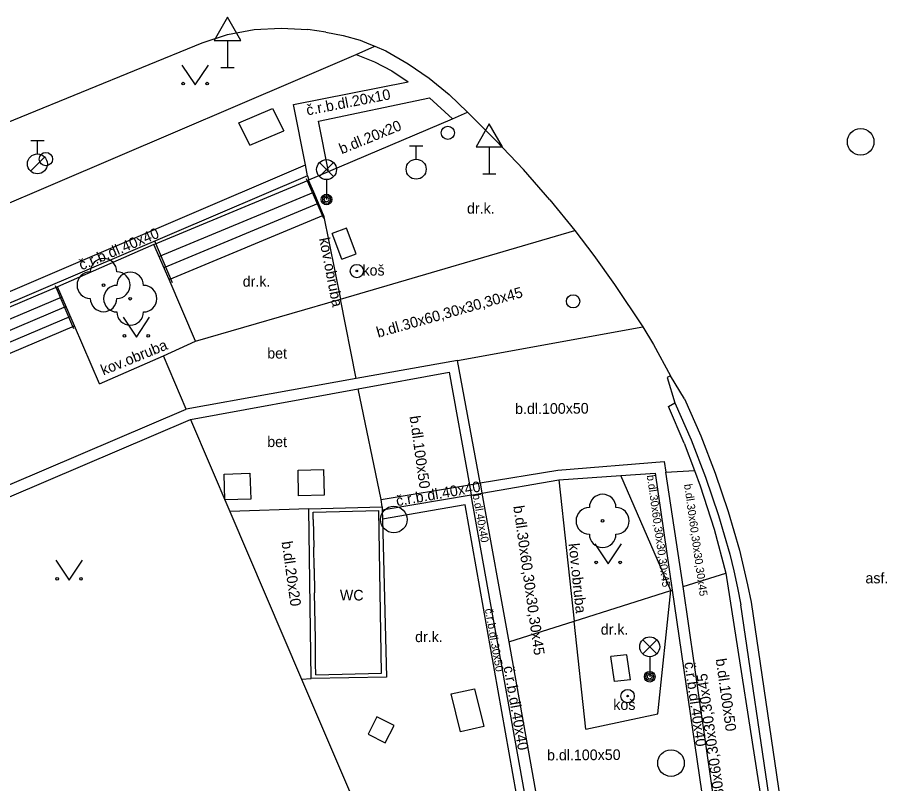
# Model space of a CAD drawing. Extents: x -600309 to -598967, y -1161267 to -1160292.
# Drawn here: x -599340.27 to -599307.71, y -1161175.51 to -1161146.69 of the extents above; entities that cross this region are included whole.
import ezdxf

# ---------------------------------------------------------------- set-up
doc = ezdxf.new("R2010")
doc.units = 0
for name, color, linetype in [('Level 10', 7, 'Continuous'), ('Level 11', 7, 'Continuous'), ('Level 22', 7, 'Continuous'), ('Level 24', 7, 'Continuous'), ('Level 25', 7, 'Continuous'), ('Level 26', 7, 'Continuous'), ('Level 27', 7, 'Continuous'), ('Level 28', 7, 'Continuous'), ('Level 31', 7, 'Continuous'), ('Level 33', 7, 'Continuous'), ('Level 34', 7, 'Continuous'), ('Level 36', 7, 'Continuous'), ('Level 40', 7, 'Continuous'), ('Level 41', 7, 'Continuous'), ('Level 42', 7, 'Continuous'), ('Level 5', 7, 'Continuous'), ('Level 6', 7, 'Continuous'), ('Level 9', 7, 'Continuous')]:
    doc.layers.add(name, color=color, linetype=linetype)

msp = doc.modelspace()

# ---------------------------------------------------------------- linework, layer by layer
at = {"layer": 'Level 10'}
for points in [[(-599333.33, -1161147.64), (-599332.37, -1161147.33), (-599331.37, -1161147.15), (-599330.36, -1161147.09), (-599329.35, -1161147.15)], [(-599328.68, -1161147.24), (-599329.35, -1161147.15)], [(-599328.68, -1161147.24), (-599328.03, -1161147.37), (-599327.38, -1161147.55)], [(-599327.38, -1161147.55), (-599327.06, -1161147.68), (-599326.83, -1161147.77), (-599326.42, -1161147.95)], [(-599344.68, -1161152.29), (-599333.33, -1161147.64)], [(-599326.42, -1161147.95), (-599325.58, -1161148.43), (-599324.79, -1161148.98), (-599324.04, -1161149.59), (-599323.35, -1161150.26)], [(-599323.35, -1161150.26), (-599322.28, -1161151.32), (-599321.25, -1161152.41)], [(-599320.26, -1161153.55), (-599321.25, -1161152.41)], [(-599320.26, -1161153.55), (-599319.32, -1161154.71), (-599318.6, -1161155.65), (-599317.82, -1161156.74)], [(-599317.82, -1161156.74), (-599316.76, -1161158.33), (-599316.36, -1161158.99), (-599315.72, -1161160.17)], [(-599315.19, -1161161.04), (-599315.72, -1161160.17)], [(-599315.19, -1161161.04), (-599314.58, -1161162.43), (-599314.04, -1161163.84), (-599313.55, -1161165.28), (-599313.13, -1161166.73)], [(-599313.13, -1161166.73), (-599312.97, -1161167.38), (-599312.82, -1161168.03), (-599312.69, -1161168.69)], [(-599312.69, -1161168.69), (-599310.5, -1161183.56)]]:
    msp.add_lwpolyline(points, dxfattribs=at)
at = {"layer": 'Level 11'}
for points in [[(-599327.53, -1161148.08), (-599326.83, -1161147.77)], [(-599329.73, -1161149.02), (-599327.53, -1161148.08)], [(-599327.53, -1161148.08), (-599326.85, -1161148.36), (-599326.19, -1161148.7), (-599325.58, -1161149.11)], [(-599343.45, -1161154.89), (-599329.73, -1161149.02)], [(-599329.89, -1161149.97), (-599325.58, -1161149.11)], [(-599328.95, -1161150.59), (-599324.78, -1161149.72)], [(-599324.78, -1161149.72), (-599323.91, -1161150.5)], [(-599329.44, -1161152.24), (-599329.89, -1161149.97)], [(-599323.91, -1161150.5), (-599323.35, -1161150.26)], [(-599329.33, -1161152.81), (-599329.31, -1161152.8), (-599328.57, -1161152.49), (-599323.91, -1161150.5)], [(-599328.57, -1161152.49), (-599328.95, -1161150.59)], [(-599348.91, -1161160.57), (-599329.44, -1161152.24)], [(-599329.36, -1161152.65), (-599329.44, -1161152.24)], [(-599329.36, -1161152.65), (-599351.42, -1161162.08)], [(-599329.36, -1161152.65), (-599329.31, -1161152.8)], [(-599335.14, -1161155.23), (-599329.33, -1161152.81)], [(-599329.13, -1161153.26), (-599329.33, -1161152.81)], [(-599334.95, -1161155.68), (-599329.13, -1161153.26)], [(-599328.95, -1161153.68), (-599329.13, -1161153.26)], [(-599334.76, -1161156.1), (-599328.95, -1161153.68)], [(-599328.76, -1161154.13), (-599328.95, -1161153.68)], [(-599334.57, -1161156.55), (-599328.76, -1161154.13)], [(-599328.76, -1161154.13), (-599328.13, -1161157.29)], [(-599328.13, -1161157.29), (-599319.32, -1161154.71)], [(-599335.14, -1161155.23), (-599338.77, -1161156.82)], [(-599333.57, -1161158.87), (-599334.57, -1161156.55), (-599335.14, -1161155.23)], [(-599338.77, -1161156.82), (-599351.32, -1161162.15)], [(-599338.13, -1161158.29), (-599338.77, -1161156.82)], [(-599338.6, -1161157.21), (-599351.14, -1161162.53)], [(-599333.57, -1161158.87), (-599328.13, -1161157.29)], [(-599327.53, -1161160.27), (-599328.13, -1161157.29)], [(-599338.44, -1161157.57), (-599350.99, -1161162.9)], [(-599338.28, -1161157.94), (-599350.84, -1161163.27)], [(-599343.98, -1161160.78), (-599338.13, -1161158.29)], [(-599337.19, -1161160.47), (-599338.13, -1161158.29)], [(-599323.73, -1161159.59), (-599316.76, -1161158.33)], [(-599334.78, -1161159.42), (-599333.57, -1161158.87)], [(-599337.19, -1161160.47), (-599334.78, -1161159.42)], [(-599333.93, -1161161.43), (-599334.78, -1161159.42)], [(-599323.73, -1161159.59), (-599327.53, -1161160.27)], [(-599322.88, -1161164.2), (-599323.73, -1161159.59)], [(-599327.46, -1161160.66), (-599324.04, -1161160.04)], [(-599324.04, -1161160.04), (-599323.27, -1161164.27)], [(-599315.72, -1161160.17), (-599315.85, -1161160.24)], [(-599315.85, -1161160.24), (-599315.55, -1161161.19)], [(-599327.53, -1161160.27), (-599333.93, -1161161.43)], [(-599333.77, -1161161.81), (-599327.46, -1161160.66)], [(-599326.6, -1161164.83), (-599327.46, -1161160.66)], [(-599315.8, -1161161.32), (-599315.55, -1161161.19)], [(-599315.55, -1161161.19), (-599314.94, -1161162.58), (-599314.4, -1161163.99), (-599313.91, -1161165.43), (-599313.49, -1161166.88)], [(-599348.49, -1161167.65), (-599333.93, -1161161.43)], [(-599315.21, -1161162.71), (-599315.8, -1161161.32)], [(-599348.68, -1161168.18), (-599333.77, -1161161.81)], [(-599333.77, -1161161.81), (-599332.29, -1161165.28)], [(-599315.21, -1161162.71), (-599314.82, -1161163.73), (-599314.6, -1161164.31), (-599314.08, -1161165.94), (-599313.64, -1161167.6)], [(-599319.95, -1161163.72), (-599315.96, -1161163.39)], [(-599315.96, -1161163.39), (-599315.9, -1161163.8)], [(-599322.88, -1161164.2), (-599319.95, -1161163.72)], [(-599317.58, -1161163.92), (-599316.3, -1161163.83)], [(-599316.3, -1161163.83), (-599315.66, -1161168.23), (-599314.38, -1161177)], [(-599315.9, -1161163.8), (-599314.82, -1161163.73)], [(-599315.24, -1161168.1), (-599315.9, -1161163.8)], [(-599322.81, -1161164.59), (-599319.92, -1161164.09)], [(-599319.92, -1161164.09), (-599317.58, -1161163.92)], [(-599319.92, -1161164.09), (-599319.34, -1161169.4)], [(-599315.71, -1161168.25), (-599317.58, -1161163.92)], [(-599326.6, -1161164.83), (-599323.27, -1161164.27)], [(-599323.27, -1161164.27), (-599322.88, -1161164.2)], [(-599323.27, -1161164.27), (-599323.21, -1161164.66)], [(-599322.88, -1161164.2), (-599322.81, -1161164.59)], [(-599323.21, -1161164.66), (-599326.56, -1161165.23)], [(-599323.21, -1161164.66), (-599322.81, -1161164.59)], [(-599320.92, -1161177.44), (-599323.21, -1161164.66)], [(-599322.81, -1161164.59), (-599321.8, -1161170.18), (-599320.5, -1161177.41)], [(-599326.56, -1161165.1), (-599326.6, -1161164.83)], [(-599323.44, -1161165.03), (-599326.55, -1161165.57)], [(-599321.23, -1161177.46), (-599323.44, -1161165.03)], [(-599329.32, -1161165.18), (-599332.29, -1161165.28)], [(-599332.29, -1161165.28), (-599329.59, -1161171.58)], [(-599313.49, -1161166.88), (-599313.34, -1161167.51), (-599313.2, -1161168.15), (-599313.08, -1161168.79)], [(-599315.24, -1161168.1), (-599313.64, -1161167.6)], [(-599313.64, -1161167.6), (-599312.2, -1161176.85)], [(-599319.34, -1161169.4), (-599315.71, -1161168.25)], [(-599316.2, -1161172.89), (-599315.71, -1161168.25)], [(-599315.71, -1161168.25), (-599315.66, -1161168.23)], [(-599313.96, -1161176.97), (-599315.24, -1161168.1)], [(-599310.84, -1161183.94), (-599313.08, -1161168.79)], [(-599321.8, -1161170.18), (-599319.34, -1161169.4)], [(-599318.9, -1161173.46), (-599319.34, -1161169.4)], [(-599329.59, -1161171.58), (-599329.23, -1161171.56)], [(-599329.59, -1161171.58), (-599327.07, -1161177.46)], [(-599318.9, -1161173.46), (-599316.2, -1161172.89)]]:
    msp.add_lwpolyline(points, dxfattribs=at)
at = {"layer": 'Level 22'}
for centre in [(-599337.03, -1161156.76), (-599336.03, -1161157.27), (-599318.27, -1161165.63)]:
    msp.add_circle(centre, 0.05, dxfattribs=at)
for centre, start, end in [((-599337.03, -1161156.26), 0, 180), ((-599337.53, -1161156.76), 90, 270), ((-599336.53, -1161156.76), 270, 90), ((-599336.03, -1161156.77), 0, 180), ((-599336.53, -1161157.27), 90, 270), ((-599335.53, -1161157.27), 270, 90), ((-599337.03, -1161157.26), 180, 0), ((-599336.03, -1161157.77), 180, 0), ((-599318.27, -1161165.13), 0, 180), ((-599318.77, -1161165.63), 90, 270), ((-599317.77, -1161165.63), 270, 90), ((-599318.27, -1161166.13), 180, 0)]:
    msp.add_arc(centre, 0.5, start, end, dxfattribs=at)
at = {"layer": 'Level 24'}
for points in [[(-599327.9, -1161154.62), (-599328.44, -1161154.82)], [(-599327.54, -1161155.58), (-599327.9, -1161154.62)], [(-599328.08, -1161155.78), (-599328.44, -1161154.82)], [(-599328.08, -1161155.78), (-599327.54, -1161155.58)], [(-599329.32, -1161165.18), (-599326.56, -1161165.1)], [(-599326.56, -1161165.1), (-599326.56, -1161165.23), (-599326.55, -1161165.57), (-599326.4, -1161171.51)], [(-599329.23, -1161171.56), (-599329.32, -1161165.18)], [(-599317.36, -1161170.67), (-599317.96, -1161170.73)], [(-599317.22, -1161171.61), (-599317.36, -1161170.67)], [(-599317.82, -1161171.67), (-599317.96, -1161170.73)], [(-599326.4, -1161171.51), (-599329.23, -1161171.56)], [(-599317.22, -1161171.61), (-599317.82, -1161171.67)]]:
    msp.add_lwpolyline(points, dxfattribs=at)
at = {"layer": 'Level 25'}
for centre, radius in [((-599327.51, -1161156.23), 0.25), ((-599327.51, -1161156.23), 0.0303), ((-599317.33, -1161172.22), 0.25), ((-599317.33, -1161172.22), 0.0303)]:
    msp.add_circle(centre, radius, dxfattribs=at)
at = {"layer": 'Level 26'}
for points in [[(-599331.95, -1161150.65), (-599330.68, -1161150.11)], [(-599330.68, -1161150.11), (-599330.26, -1161150.96)], [(-599331.53, -1161151.5), (-599331.95, -1161150.65)], [(-599331.53, -1161151.5), (-599330.26, -1161150.96)], [(-599332.5, -1161163.87), (-599331.53, -1161163.83)], [(-599331.53, -1161163.83), (-599331.5, -1161164.81)], [(-599329.72, -1161163.72), (-599328.76, -1161163.7)], [(-599329.71, -1161164.69), (-599329.72, -1161163.72)], [(-599328.76, -1161163.7), (-599328.74, -1161164.66)], [(-599332.47, -1161164.84), (-599332.5, -1161163.87)], [(-599331.5, -1161164.81), (-599332.47, -1161164.84)], [(-599328.74, -1161164.66), (-599329.71, -1161164.69)], [(-599323.96, -1161172.13), (-599323.09, -1161171.95)], [(-599323.09, -1161171.95), (-599322.74, -1161173.36)], [(-599323.62, -1161173.56), (-599323.96, -1161172.13)], [(-599326.76, -1161173), (-599327.09, -1161173.65)], [(-599326.11, -1161173.33), (-599326.76, -1161173)], [(-599326.44, -1161173.98), (-599326.11, -1161173.33)], [(-599322.74, -1161173.36), (-599323.62, -1161173.56)], [(-599327.09, -1161173.65), (-599326.44, -1161173.98)]]:
    msp.add_lwpolyline(points, dxfattribs=at)
at = {"layer": 'Level 27'}
for centre in [(-599308.57, -1161151.37), (-599326.12, -1161165.58), (-599315.7, -1161174.74)]:
    msp.add_circle(centre, 0.5, dxfattribs=at)
at = {"layer": 'Level 28'}
for p, q in [((-599339.77, -1161151.325), (-599339.27, -1161151.325)), ((-599339.52, -1161151.825), (-599339.52, -1161151.325)), ((-599325.53, -1161151.525), (-599325.03, -1161151.525)), ((-599325.28, -1161152.025), (-599325.28, -1161151.525)), ((-599339.778, -1161152.472), (-599339.248, -1161151.942))]:
    msp.add_line(p, q, dxfattribs=at)
for centre, radius in [((-599324.09, -1161151.03), 0.25), ((-599339.2, -1161152.02), 0.25), ((-599339.52, -1161152.2), 0.375), ((-599325.28, -1161152.4), 0.375)]:
    msp.add_circle(centre, radius, dxfattribs=at)
at = {"layer": 'Level 31'}
msp.add_circle((-599319.38, -1161157.37), 0.25, dxfattribs=at)
at = {"layer": 'Level 33'}
for p, q in [((-599328.915, -1161152.68), (-599328.385, -1161152.15)), ((-599328.915, -1161152.15), (-599328.385, -1161152.68)), ((-599328.65, -1161152.79), (-599328.65, -1161153.54)), ((-599316.765, -1161170.63), (-599316.235, -1161170.1)), ((-599316.765, -1161170.1), (-599316.235, -1161170.63)), ((-599316.5, -1161170.74), (-599316.5, -1161171.49))]:
    msp.add_line(p, q, dxfattribs=at)
for centre, radius in [((-599328.65, -1161152.415), 0.375), ((-599328.65, -1161153.54), 0.2), ((-599328.65, -1161153.54), 0.1445), ((-599328.65, -1161153.54), 0.0876), ((-599316.5, -1161170.365), 0.375), ((-599316.5, -1161171.49), 0.2), ((-599316.5, -1161171.49), 0.1445), ((-599316.5, -1161171.49), 0.0876)]:
    msp.add_circle(centre, radius, dxfattribs=at)
at = {"layer": 'Level 34'}
for p, q in [((-599332.37, -1161147.552), (-599332.37, -1161148.57)), ((-599332.62, -1161148.57), (-599332.12, -1161148.57)), ((-599322.53, -1161151.562), (-599322.53, -1161152.58)), ((-599322.78, -1161152.58), (-599322.28, -1161152.58))]:
    msp.add_line(p, q, dxfattribs=at)
for points in [[(-599332.87, -1161147.552), (-599331.87, -1161147.552), (-599332.37, -1161146.686)], [(-599323.03, -1161151.562), (-599322.03, -1161151.562), (-599322.53, -1161150.696)]]:
    msp.add_lwpolyline(points, close=True, dxfattribs=at)
at = {"layer": 'Level 36'}
for points in [[(-599334.09, -1161148.48), (-599333.59, -1161149.23), (-599333.09, -1161148.48)], [(-599336.3, -1161157.97), (-599335.8, -1161158.72), (-599335.3, -1161157.97)], [(-599318.56, -1161166.49), (-599318.06, -1161167.24), (-599317.56, -1161166.49)], [(-599338.83, -1161167.11), (-599338.33, -1161167.86), (-599337.83, -1161167.11)]]:
    msp.add_lwpolyline(points, dxfattribs=at)
for centre in [(-599334.0402, -1161149.1798), (-599333.1408, -1161149.1798), (-599336.2502, -1161158.6698), (-599335.3508, -1161158.6698), (-599318.5102, -1161167.1898), (-599317.6108, -1161167.1898), (-599338.7802, -1161167.8098), (-599337.8808, -1161167.8098)]:
    msp.add_circle(centre, 0.05, dxfattribs=at)
at = {"layer": 'Level 5'}
for points in [[(-599329.15, -1161165.3), (-599326.68, -1161165.24)], [(-599329.15, -1161165.58), (-599329.15, -1161165.3)], [(-599326.58, -1161171.36), (-599326.68, -1161165.24)], [(-599329.12, -1161167.42), (-599329.13, -1161166.62)], [(-599329.07, -1161170.08), (-599329.1, -1161168.33)], [(-599329.05, -1161171.42), (-599329.06, -1161170.99)], [(-599329.05, -1161171.42), (-599326.58, -1161171.36)]]:
    msp.add_lwpolyline(points, dxfattribs=at)
at = {"layer": 'Level 6'}
for points in [[(-599329.15, -1161165.58), (-599329.13, -1161166.62)], [(-599329.12, -1161167.42), (-599329.1, -1161168.33)], [(-599329.06, -1161170.99), (-599329.07, -1161170.08)]]:
    msp.add_lwpolyline(points, dxfattribs=at)
at = {"layer": 'Level 9'}
for points in [[(-599328.75, -1161154.26), (-599329.4, -1161152.76)], [(-599334.44, -1161156.68), (-599335.1, -1161155.11)], [(-599338.15, -1161158.41), (-599338.84, -1161156.79)]]:
    msp.add_lwpolyline(points, dxfattribs=at)

# ---------------------------------------------------------------- texts
at = {"layer": 'Level 40'}
for s, height, rotation, p in [('č.r.b.dl.20x10', 0.39999, 11.06112, (-599329.37, -1161150.38)), ('b.dl.20x20', 0.39999, 22.14837, (-599328.08, -1161151.84)), ('č.r.b.dl.40x40', 0.39999, 23, (-599337.86, -1161156.21)), ('b.dl.30x60,30x30,30x45', 0.39999, 15.69461, (-599326.71, -1161158.74)), ('bet', 0.39999, 359.66917, (-599330.88, -1161159.52)), ('b.dl.100x50', 0.39999, 0.36034, (-599321.56, -1161161.61)), ('b.dl.100x50', 0.39999, 278, (-599325.53, -1161161.7)), ('bet', 0.39999, 359.66917, (-599330.88, -1161162.85)), ('č.r.b.dl.40x40', 0.39999, 10, (-599326, -1161165.08)), ('b.dl.30x60,30x30,30x45', 0.3, 278, (-599316.61, -1161163.92)), ('b.dl.30x60,30x30,30x45', 0.3, 278, (-599315.21, -1161164.26)), ('b.dl.40x40', 0.3, 280, (-599323.16, -1161164.64)), ('b.dl.30x60,30x30,30x45', 0.39999, 278, (-599321.63, -1161165.08)), ('b.dl.20x20', 0.39999, 278, (-599330.34, -1161166.42)), ('č.r.b.dl.30x50', 0.3, 280, (-599322.7, -1161168.95)), ('č.r.b.dl.40x40', 0.39999, 278, (-599315.2, -1161170.96)), ('b.dl.100x50', 0.4, 278, (-599314.02, -1161170.83)), ('č.r.b.dl.40x40', 0.39999, 280, (-599322, -1161171.12)), ('b.dl.30x60,30x30,30x45', 0.39999, 98, (-599313.56, -1161176.97)), ('b.dl.100x50', 0.39999, 0.36034, (-599320.36, -1161174.64))]:
    msp.add_text(s, height=height, rotation=rotation, dxfattribs=at).set_placement(p)
for s, height, p in [('dr.k.', 0.39999, (-599323.37, -1161154.07)), ('dr.k.', 0.39999, (-599331.8, -1161156.82)), ('asf.', 0.4, (-599308.39, -1161167.98)), ('dr.k.', 0.39999, (-599318.34, -1161169.91)), ('dr.k.', 0.39999, (-599325.32, -1161170.19))]:
    msp.add_text(s, height=height, dxfattribs=at).set_placement(p)
at = {"layer": 'Level 41'}
msp.add_text('WC', height=0.39999, rotation=359.66917, dxfattribs=at).set_placement((-599328.15, -1161168.62))
at = {"layer": 'Level 42'}
for rotation, p in [(281, (-599328.93, -1161155.01)), (22.14837, (-599337.04, -1161160.16)), (276, (-599319.55, -1161166.49))]:
    msp.add_text('kov.obruba', height=0.39999, rotation=rotation, dxfattribs=at).set_placement(p)
for p in [(-599327.3, -1161156.4), (-599317.87, -1161172.74)]:
    msp.add_text('koš', height=0.39999, dxfattribs=at).set_placement(p)

doc.saveas('drawing.dxf')
